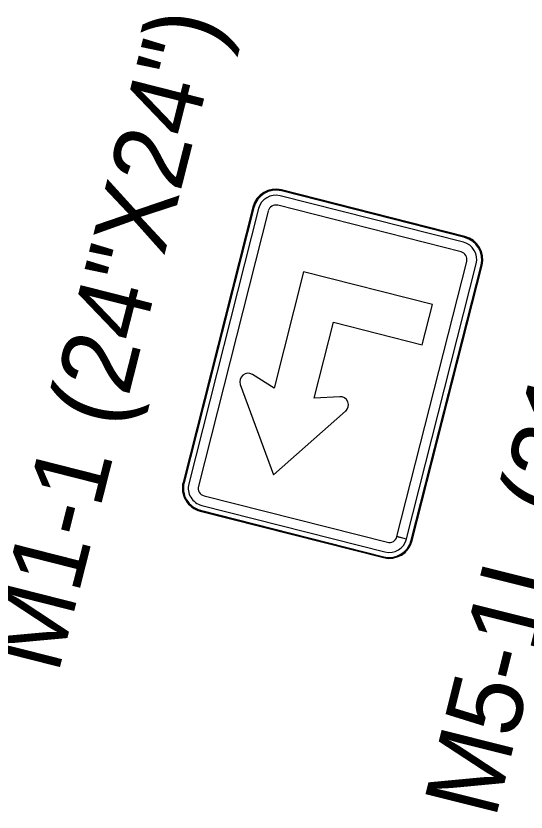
# Model space of a CAD drawing. Extents: x 670257 to 671518, y 737783 to 738188.
# Drawn here: x 670274.242 to 670275.967, y 738176.418 to 738179.109 of the extents above; entities that cross this region are included whole.
import ezdxf

# ---------------------------------------------------------------- set-up
doc = ezdxf.new("R2010")
doc.units = 0
doc.layers.add('Default', color=7, linetype='Continuous')
doc.layers.add('R_SIGN_ANNOT', color=7, linetype='Continuous')

msp = doc.modelspace()

# ---------------------------------------------------------------- linework, layer by layer
at = {"layer": 'Default'}
for p, q in [((670275.7552, 738178.3438), (670275.1355, 738178.501)), ((670275.1396, 738178.5172), (670275.1396, 738178.5172)), ((670275.7593, 738178.36), (670275.1396, 738178.5172)), ((670275.7601, 738178.3632), (670275.1404, 738178.5204)), ((670275.7601, 738178.3632), (670275.1404, 738178.5204)), ((670275.0433, 738178.4625), (670274.8074, 738177.5325)), ((670275.0433, 738178.4625), (670274.8074, 738177.5325)), ((670275.0465, 738178.4617), (670274.8106, 738177.5317)), ((670275.0626, 738178.4576), (670274.8267, 738177.5276)), ((670275.0949, 738178.4494), (670274.859, 738177.5194)), ((670275.0465, 738178.4617), (670275.0465, 738178.4617)), ((670275.747, 738178.3115), (670275.1273, 738178.4687)), ((670275.7593, 738178.36), (670275.7593, 738178.36)), ((670275.5304, 738177.3495), (670275.7663, 738178.2791)), ((670275.5627, 738177.3413), (670275.7985, 738178.271)), ((670275.5788, 738177.3369), (670275.8147, 738178.2669)), ((670275.582, 738177.336), (670275.8179, 738178.266)), ((670275.582, 738177.3361), (670275.8179, 738178.266)), ((670275.8147, 738178.2669), (670275.8147, 738178.2669)), ((670275.3369, 738177.8219), (670275.2505, 738177.8168)), ((670275.3369, 738177.8219), (670275.2505, 738177.8168)), ((670275.3369, 738177.8219), (670275.2505, 738177.8168)), ((670274.8106, 738177.5317), (670274.8106, 738177.5317)), ((670274.8783, 738177.4871), (670275.498, 738177.3299)), ((670274.8701, 738177.4548), (670275.4898, 738177.2976)), ((670274.8652, 738177.4354), (670275.4849, 738177.2782)), ((670274.8652, 738177.4354), (670275.4849, 738177.2782)), ((670274.866, 738177.4386), (670275.4857, 738177.2814)), ((670274.866, 738177.4386), (670274.866, 738177.4386)), ((670275.5304, 738177.3495), (670275.5627, 738177.3413)), ((670275.5626, 738177.341), (670275.5304, 738177.3491)), ((670275.582, 738177.336), (670275.5788, 738177.3369)), ((670275.5788, 738177.3369), (670275.5788, 738177.3369)), ((670275.5788, 738177.3369), (670275.582, 738177.3361)), ((670275.4857, 738177.2814), (670275.4857, 738177.2814))]:
    msp.add_line(p, q, dxfattribs=at)
for points in [[(670275.2505, 738177.8168), (670275.3157, 738178.0738), (670275.6158, 738177.9977), (670275.6502, 738178.1333), (670275.2145, 738178.2438), (670275.1149, 738177.8512), (670275.0415, 738177.8968)], [(670275.2505, 738177.8168), (670275.3157, 738178.0738), (670275.6158, 738177.9977), (670275.6502, 738178.1333), (670275.2145, 738178.2438), (670275.1149, 738177.8512), (670275.0415, 738177.8968)], [(670275.2505, 738177.8168), (670275.3157, 738178.0738), (670275.6158, 738177.9977), (670275.6502, 738178.1333), (670275.2145, 738178.2438), (670275.1149, 738177.8512), (670275.0415, 738177.8968)], [(670275.0004, 738177.8634), (670275.1128, 738177.5582), (670275.3569, 738177.773)], [(670275.0004, 738177.8634), (670275.1128, 738177.5582), (670275.3569, 738177.773)], [(670275.0004, 738177.8634), (670275.1128, 738177.5582), (670275.3569, 738177.773)]]:
    msp.add_lwpolyline(points, dxfattribs=at)
for centre, major_axis, start_param, end_param in [((670275.1207, 738178.4429), (0.0197, 0.0775), 0, 1.570796), ((670275.1207, 738178.4429), (0.0197, 0.0775), 0, 1.570796), ((670275.1207, 738178.4429), (0.0188, 0.0743), 0, 1.570796), ((670275.1207, 738178.4429), (0.0147, 0.0581), 0, 1.570796), ((670275.1207, 738178.4429), (0.0066, 0.0258), 0, 1.570796), ((670275.7404, 738178.2857), (0.0197, 0.0775), 4.712389, 6.283185), ((670275.7404, 738178.2857), (0.0197, 0.0775), 4.712389, 6.283185), ((670275.7404, 738178.2857), (0.0147, 0.0581), 4.712389, 6.283185), ((670275.7404, 738178.2857), (0.0188, 0.0743), 4.712389, 6.283185), ((670275.7404, 738178.2857), (0.0066, 0.0258), 4.712389, 6.283185), ((670275.0267, 738177.8731), (0.0069, 0.0271), 5.975991, 8.455234), ((670275.0267, 738177.8731), (0.0069, 0.0271), 5.975991, 8.455234), ((670275.0267, 738177.8731), (0.0069, 0.0271), 5.975991, 8.455234), ((670275.3385, 738177.794), (0.0069, 0.0271), 4.111136, 6.59038), ((670275.3385, 738177.794), (0.0069, 0.0271), 4.111136, 6.59038), ((670275.3385, 738177.794), (0.0069, 0.0271), 4.111136, 6.59038), ((670274.8848, 738177.5129), (0.0197, 0.0775), 1.570796, 3.141593), ((670274.8848, 738177.5129), (0.0197, 0.0775), 1.570796, 3.141593), ((670274.8848, 738177.5129), (0.0188, 0.0743), 1.570796, 3.141593), ((670274.8848, 738177.5129), (0.0147, 0.0581), 1.570796, 3.141593), ((670274.8848, 738177.5129), (0.0066, 0.0258), 1.570796, 3.141593), ((670275.5045, 738177.3557), (0.0147, 0.0581), 3.141593, 4.712389), ((670275.5045, 738177.3557), (0.0066, 0.0258), 3.141593, 4.712389), ((670275.5045, 738177.3557), (0.0197, 0.0775), 3.141593, 4.712389), ((670275.5045, 738177.3557), (0.0197, 0.0775), 3.141593, 4.712389), ((670275.5045, 738177.3557), (0.0188, 0.0743), 3.141593, 4.712389)]:
    msp.add_ellipse(centre, major_axis=major_axis, ratio=0.999544, start_param=start_param, end_param=end_param, dxfattribs=at)

# ---------------------------------------------------------------- texts
msp.add_text('M5-1L (21"X15")', height=0.25, rotation=75.9504, dxfattribs=at).set_placement((670275.8627, 738176.3918))
at = {"layer": 'R_SIGN_ANNOT'}
msp.add_text('M1-1 (24"X24")', height=0.25, rotation=75.7686, dxfattribs=at).set_placement((670274.3844, 738176.8817))

doc.saveas('drawing.dxf')
